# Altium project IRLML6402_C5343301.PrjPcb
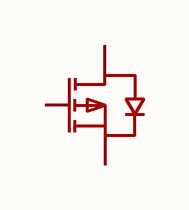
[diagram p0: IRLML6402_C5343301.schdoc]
1 sheet, 1 parts. Net scope: global (net labels, ports and power ports of the same name join across sheets).

## Sheet IRLML6402_C5343301.schdoc
size 127 x 101 mm

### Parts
Q?  irlml6402_c5343301  [SOT-23-3_L2.9-W1.3-P1.90-LS2.4-BR]  (value not drawn)

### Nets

Not connected (* = marked no-connect by the designer): Q? 1(G) 2(S) 3(D)

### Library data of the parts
Q? = irlml6402_c5343301: 数量:1个P沟道;漏源电压(Vdss):20V;连续漏极电流(Id):4A;导通电阻(RDS(on)):50mΩ@4.5V;耗散功率(Pd):1.56W;阈值电压(Vgs(th)):650mV;; Manufacturer: MSKSEMI(美森科); AddInBom: yes; ModelId: c62791f0466c4ae2a892c056b845b0ca; ModelName: SOT-23-3P_L2.9-W1.3-H1.0-LS2.4-P0.95; ModelTransform: 98.425,114.173,0,180,0,0,0.0005,-0.0005,0; Number: 1个P沟道; Drain to Source Voltage: 20V; Current - Continuous Drain(Id): 4A; Pd - Power Dissipation: 1.56W; Gate Threshold Voltage (Vgs(th)): 650mV; Gate Charge(Qg): 9.6nC@4.5V; Input Capacitance(Ciss): 850pF; Reverse Transfer Capacitance (Crss@Vds): 55pF; Type: P沟道; Output Capacitance(Coss): 70pF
